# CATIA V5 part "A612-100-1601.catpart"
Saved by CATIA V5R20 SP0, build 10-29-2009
Part number: A612-100-1601
Source: Unknown
Property "A": "30.000"
Property "ARTICLENO": "A612-100-1601"
Property "B": "40.000"
Property "BOMINFO": "A612-100-1601"
Property "CODE": "A612-100-1601"
Property "D": "22.000"
Property "FORM": "A"
Property "L": "160.000"
Property "L1": "45.000"
Property "L2": "70.000"
Property "L3": "0.000"
Property "LINA": "A612-100-1601"
Property "NB": "A612-100-1601"
Property "NBSYN": "$CODE."
Property "NN": "A612"
Property "NT": "CDI 3357 E-Type Wear Plates, steel and self-lubricating"
Property "SUPPLIER": "CF"
Property "T": "30.000"
Property "W": "100.000"
Bounding box of the stored display mesh (mm): x 0 to 30, y 0 to 160, z 0 to 100
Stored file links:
  C:\Users\Utente\Desktop\3D files A612\A612-100-1601.catpart
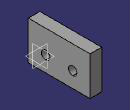
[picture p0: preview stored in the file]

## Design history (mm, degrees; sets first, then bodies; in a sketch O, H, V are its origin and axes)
Body1 "Geometry.1" (main body)
  Solid1 "A612-100-1601.catpart": solid without history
